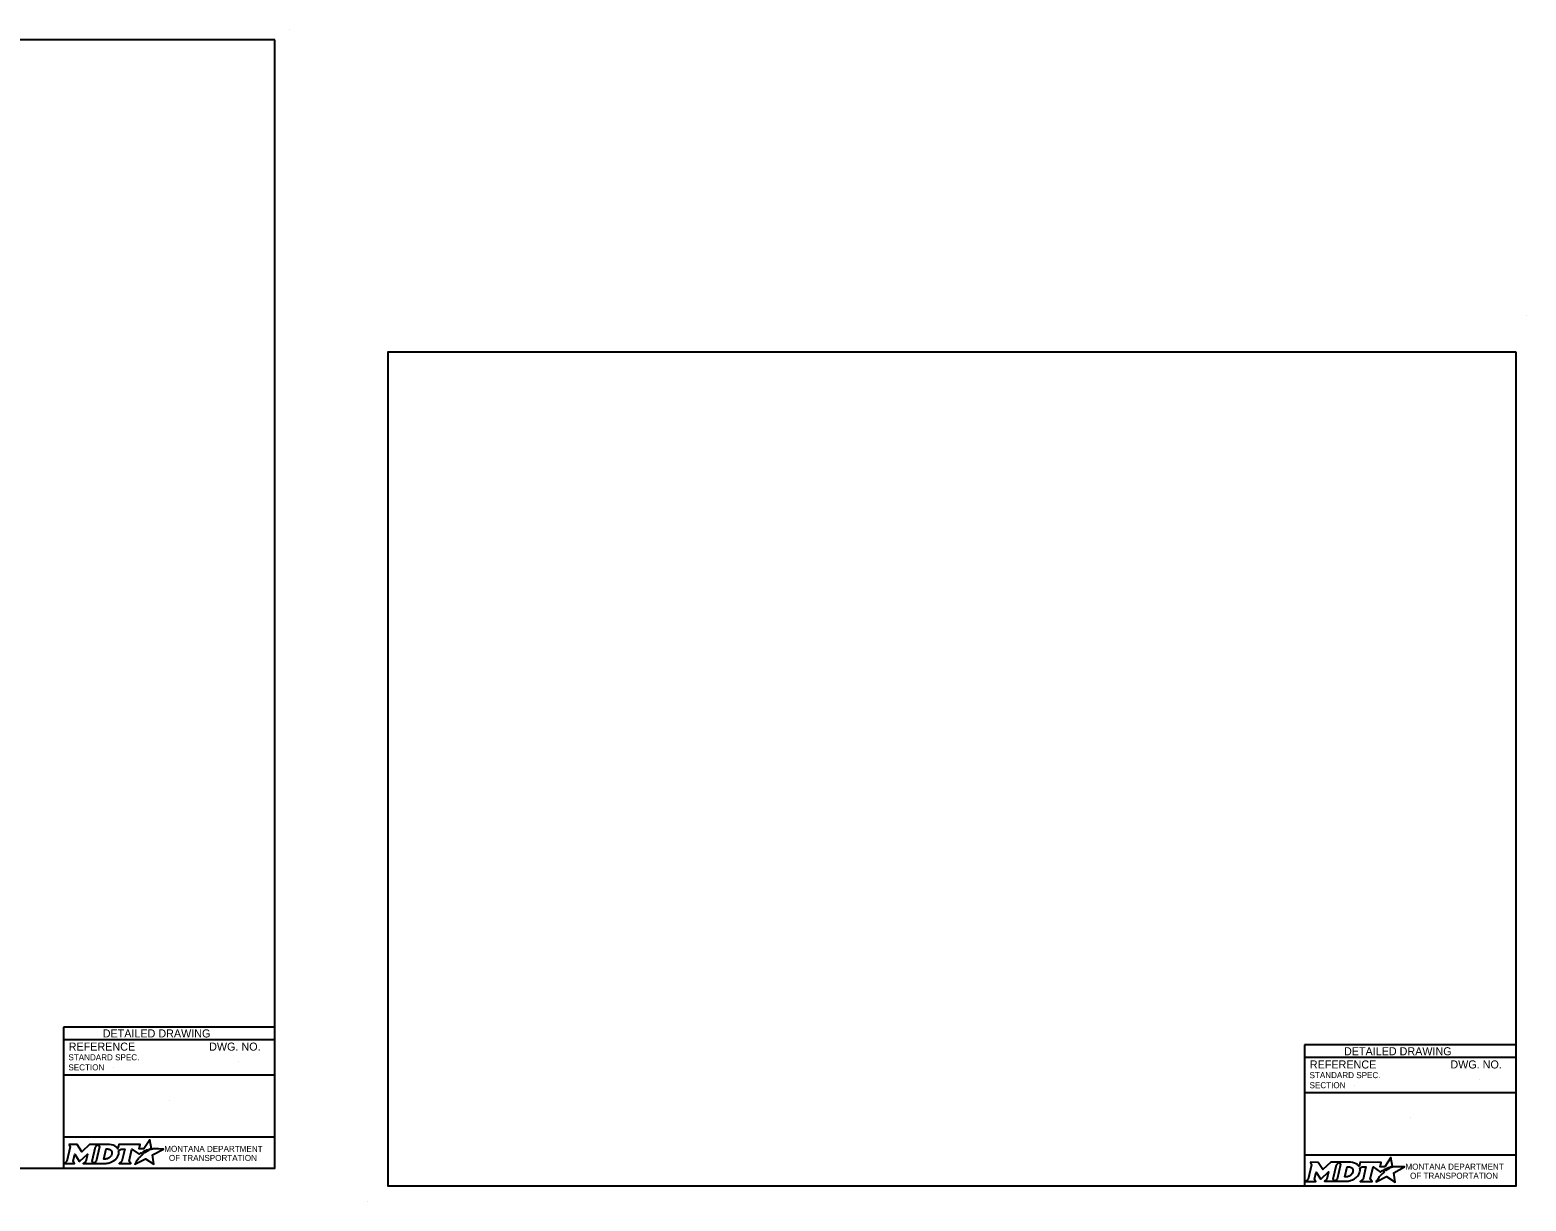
# Model space of a CAD drawing. Extents: x 49991.4 to 50021, y 49987.6 to 50011.4.
# Drawn here: x 50006.18 to 50021.04, y 49999.74 to 50011.36 of the extents above; entities that cross this region are included whole.
import ezdxf

# ---------------------------------------------------------------- set-up
doc = ezdxf.new("R2010")
doc.units = 0
for name, color, linetype in [('Default', 7, 'Continuous'), ('Level 1', 7, 'Continuous'), ('Level 2', 7, 'Continuous'), ('Level 4', 7, 'Continuous')]:
    doc.layers.add(name, color=color, linetype=linetype)

msp = doc.modelspace()

# ---------------------------------------------------------------- linework, layer by layer
at = {"layer": 'Default'}
for points in [[(50018.893, 50000.121), (50018.907, 50000.097), (50018.874, 49999.954), (50018.848, 49999.931), (50018.95, 49999.931), (50018.936, 49999.954), (50018.952, 50000.024), (50018.996, 49999.955), (50019.002, 49999.955), (50019.077, 50000.025), (50019.06, 49999.954), (50019.035, 49999.932), (50019.137, 49999.932), (50019.123, 49999.955), (50019.156, 50000.097)], [(50019.156, 50000.097), (50019.182, 50000.121), (50019.099, 50000.121), (50019.02, 50000.048), (50018.975, 50000.12), (50018.893, 50000.121)], [(50019.295, 50000.121), (50019.182, 50000.121), (50019.196, 50000.098), (50019.163, 49999.954), (50019.137, 49999.932), (50019.248, 49999.932)], [(50019.319, 50000.034), (50019.318, 50000.026), (50019.315, 50000.017), (50019.311, 50000.008), (50019.305, 50000.001), (50019.299, 49999.994), (50019.291, 49999.988), (50019.282, 49999.983), (50019.273, 49999.979), (50019.264, 49999.977), (50019.255, 49999.976), (50019.239, 49999.976), (50019.263, 50000.076), (50019.279, 50000.076), (50019.286, 50000.075), (50019.294, 50000.073), (50019.301, 50000.07), (50019.307, 50000.066), (50019.311, 50000.061), (50019.315, 50000.055), (50019.318, 50000.049), (50019.319, 50000.042), (50019.32, 50000.038), (50019.319, 50000.034)], [(50019.7, 50000.068), (50019.69, 50000.074), (50019.702, 50000.076), (50019.713, 50000.078), (50019.696, 50000.168), (50019.636, 50000.077), (50019.589, 50000.076), (50019.599, 50000.12), (50019.39, 50000.121), (50019.38, 50000.078), (50019.374, 50000.086)], [(50019.387, 50000.062), (50019.411, 50000.075), (50019.448, 50000.075), (50019.42, 49999.954), (50019.392, 49999.931), (50019.508, 49999.931), (50019.491, 49999.954), (50019.52, 50000.075), (50019.591, 50000.023), (50019.612, 50000.038), (50019.632, 50000.027)], [(50019.576, 49999.971), (50019.561, 49999.947), (50019.556, 49999.939), (50019.55, 49999.931), (50019.548, 49999.926), (50019.653, 49999.979), (50019.737, 49999.924), (50019.724, 50000.017), (50019.831, 50000.075), (50019.782, 50000.076), (50019.751, 50000.077), (50019.731, 50000.077), (50019.724, 50000.075), (50019.719, 50000.074), (50019.711, 50000.072), (50019.7, 50000.068)], [(50019.65, 50000.04), (50019.648, 50000.039), (50019.629, 50000.048), (50019.639, 50000.054), (50019.644, 50000.056), (50019.652, 50000.06), (50019.658, 50000.063), (50019.666, 50000.066), (50019.673, 50000.068), (50019.685, 50000.061), (50019.681, 50000.059), (50019.676, 50000.056), (50019.672, 50000.054), (50019.667, 50000.051), (50019.665, 50000.05), (50019.662, 50000.049), (50019.66, 50000.047), (50019.658, 50000.046), (50019.655, 50000.044), (50019.652, 50000.042), (50019.65, 50000.04)], [(50019.293, 49999.939), (50019.302, 49999.942), (50019.315, 49999.947), (50019.335, 49999.958)], [(50019.59, 49999.987), (50019.59, 49999.987)]]:
    msp.add_lwpolyline(points, dxfattribs=at)
for centre, radius, start, end in [((50019.319, 50000.042), 0.0709, 339.5329, 15.8582), ((50019.274, 50000.059), 0.118, 300.9103, 339.1383)]:
    msp.add_arc(centre, radius, start, end, dxfattribs=at)
for centre, major_axis, ratio, start_param, end_param in [((50019.293, 50000.073), (0.0834, -0.0037), 0.568097, 0.61298, 1.570796), ((50019.349, 50000.081), (0.0361, -0.0295), 0.469099, 1.225588, 1.570796), ((50019.248, 50000.08), (0, 0.148), 0.987302, 3.139398, 3.456847), ((50019.583, 49999.979), (-0.00694, -0.00806), 0.008222, 0, 3.137361), ((50019.6, 49999.997), (-0.0098, -0.0102), 0.016458, 3.141593, 6.279097), ((50019.621, 50000.017), (-0.0112, -0.0097), 0.021651, 3.157348, 6.283185)]:
    msp.add_ellipse(centre, major_axis=major_axis, ratio=ratio, start_param=start_param, end_param=end_param, dxfattribs=at)
at = {"layer": 'Level 1'}
for p, q in [((50008.765, 50011.363), (50008.765, 50011.363)), ((50021.038, 50008.524), (50021.038, 50008.524)), ((50009.537, 49999.736), (50009.537, 49999.736))]:
    msp.add_line(p, q, dxfattribs=at)
for points in [[(50008.615, 50011.263), (50000.336, 50011.263), (50000.336, 50000.062), (50008.615, 50000.062)], [(50020.938, 50008.165), (50009.737, 50008.165), (50009.737, 49999.886), (50020.938, 49999.886)]]:
    msp.add_lwpolyline(points, close=True, dxfattribs=at)
at = {"layer": 'Level 2'}
for p, q in [((50008.615, 50001.462), (50006.515, 50001.462)), ((50006.515, 50001.462), (50006.515, 50000.062)), ((50008.615, 50001.337), (50006.515, 50001.337)), ((50008.251, 50001.122), (50008.251, 50001.122)), ((50008.615, 50000.987), (50006.515, 50000.987)), ((50007.009, 50001.063), (50007.009, 50001.063)), ((50007.565, 50000.738), (50007.565, 50000.738)), ((50008.615, 50000.369), (50006.515, 50000.369))]:
    msp.add_line(p, q, dxfattribs=at)
for points in [[(50006.57, 50000.297), (50006.584, 50000.274), (50006.551, 50000.131), (50006.525, 50000.108), (50006.627, 50000.108), (50006.613, 50000.131), (50006.629, 50000.201), (50006.673, 50000.132), (50006.678, 50000.132), (50006.753, 50000.202), (50006.737, 50000.13), (50006.712, 50000.108), (50006.814, 50000.108), (50006.8, 50000.132), (50006.833, 50000.274)], [(50006.833, 50000.274), (50006.859, 50000.297), (50006.776, 50000.297), (50006.697, 50000.224), (50006.652, 50000.297), (50006.57, 50000.297)], [(50006.972, 50000.297), (50006.859, 50000.297), (50006.873, 50000.275), (50006.839, 50000.131), (50006.814, 50000.108), (50006.925, 50000.108)], [(50006.996, 50000.211), (50006.995, 50000.203), (50006.992, 50000.193), (50006.988, 50000.185), (50006.982, 50000.178), (50006.976, 50000.171), (50006.968, 50000.164), (50006.959, 50000.16), (50006.95, 50000.156), (50006.941, 50000.154), (50006.932, 50000.153), (50006.916, 50000.153), (50006.94, 50000.253), (50006.956, 50000.253), (50006.963, 50000.252), (50006.971, 50000.25), (50006.977, 50000.247), (50006.983, 50000.243), (50006.988, 50000.238), (50006.992, 50000.232), (50006.995, 50000.226), (50006.996, 50000.218), (50006.996, 50000.215), (50006.996, 50000.211)], [(50007.377, 50000.245), (50007.367, 50000.25), (50007.378, 50000.253), (50007.39, 50000.255), (50007.373, 50000.345), (50007.313, 50000.254), (50007.266, 50000.253), (50007.276, 50000.297), (50007.067, 50000.297), (50007.057, 50000.255), (50007.051, 50000.263)], [(50007.064, 50000.238), (50007.088, 50000.251), (50007.125, 50000.251), (50007.097, 50000.131), (50007.069, 50000.108), (50007.185, 50000.108), (50007.168, 50000.131), (50007.196, 50000.251), (50007.268, 50000.2), (50007.289, 50000.215), (50007.309, 50000.204)], [(50007.253, 50000.148), (50007.237, 50000.124), (50007.233, 50000.116), (50007.227, 50000.107), (50007.225, 50000.103), (50007.33, 50000.156), (50007.414, 50000.101), (50007.401, 50000.194), (50007.508, 50000.252), (50007.458, 50000.253), (50007.428, 50000.253), (50007.407, 50000.254), (50007.401, 50000.252), (50007.396, 50000.251), (50007.387, 50000.249), (50007.377, 50000.245)], [(50007.327, 50000.217), (50007.324, 50000.215), (50007.306, 50000.225), (50007.316, 50000.231), (50007.32, 50000.233), (50007.329, 50000.237), (50007.335, 50000.239), (50007.343, 50000.243), (50007.35, 50000.245), (50007.362, 50000.238), (50007.358, 50000.236), (50007.353, 50000.233), (50007.349, 50000.231), (50007.344, 50000.228), (50007.342, 50000.227), (50007.339, 50000.225), (50007.337, 50000.224), (50007.334, 50000.222), (50007.332, 50000.221), (50007.329, 50000.219), (50007.327, 50000.217)], [(50006.97, 50000.116), (50006.979, 50000.118), (50006.992, 50000.124), (50007.012, 50000.135)], [(50007.267, 50000.164), (50007.267, 50000.164)]]:
    msp.add_lwpolyline(points, dxfattribs=at)
for centre, radius, start, end in [((50006.995, 50000.219), 0.0709, 339.5329, 15.8582), ((50006.951, 50000.236), 0.118, 300.9103, 339.1383)]:
    msp.add_arc(centre, radius, start, end, dxfattribs=at)
for centre, major_axis, ratio, start_param, end_param in [((50006.97, 50000.25), (0.0834, -0.0037), 0.568097, 0.61298, 1.570796), ((50007.026, 50000.257), (0.0361, -0.0295), 0.469099, 1.225588, 1.570796), ((50007.297, 50000.194), (-0.0112, -0.0097), 0.021651, 3.157348, 6.283185), ((50006.925, 50000.257), (0, 0.148), 0.987302, 3.139398, 3.456847), ((50007.26, 50000.156), (-0.00694, -0.00806), 0.008222, 0, 3.137361), ((50007.276, 50000.174), (-0.0098, -0.0102), 0.016458, 3.141593, 6.279097)]:
    msp.add_ellipse(centre, major_axis=major_axis, ratio=ratio, start_param=start_param, end_param=end_param, dxfattribs=at)
at = {"layer": 'Level 4'}
for p, q in [((50020.938, 50001.286), (50018.838, 50001.286)), ((50018.838, 50001.286), (50018.838, 49999.886)), ((50020.938, 50001.161), (50018.838, 50001.161)), ((50020.574, 50000.946), (50020.574, 50000.946)), ((50020.938, 50000.811), (50018.838, 50000.811)), ((50019.332, 50000.886), (50019.332, 50000.886)), ((50019.888, 50000.562), (50019.888, 50000.562)), ((50020.938, 50000.193), (50018.838, 50000.193))]:
    msp.add_line(p, q, dxfattribs=at)

# ---------------------------------------------------------------- texts
at = {"layer": 'Default'}
for s, p in [('MONTANA DEPARTMENT', (50019.84, 50000.047)), ('OF TRANSPORTATION', (50019.886, 49999.957))]:
    msp.add_text(s, height=0.06, rotation=360, dxfattribs=at).set_placement(p)
at = {"layer": 'Level 2'}
for s, height, p in [('DETAILED DRAWING', 0.0799, (50006.906, 50001.36)), ('REFERENCE', 0.08, (50006.568, 50001.229)), ('DWG. NO.', 0.08, (50007.962, 50001.229)), ('STANDARD SPEC.', 0.06, (50006.565, 50001.133)), ('SECTION', 0.06, (50006.565, 50001.033))]:
    msp.add_text(s, height=height, dxfattribs=at).set_placement(p)
for s, p in [('MONTANA DEPARTMENT', (50007.517, 50000.224)), ('OF TRANSPORTATION', (50007.563, 50000.134))]:
    msp.add_text(s, height=0.06, rotation=360, dxfattribs=at).set_placement(p)
at = {"layer": 'Level 4'}
for s, height, p in [('DETAILED DRAWING', 0.0799, (50019.23, 50001.183)), ('REFERENCE', 0.08, (50018.891, 50001.052)), ('DWG. NO.', 0.08, (50020.286, 50001.052)), ('STANDARD SPEC.', 0.06, (50018.888, 50000.956)), ('SECTION', 0.06, (50018.888, 50000.856))]:
    msp.add_text(s, height=height, dxfattribs=at).set_placement(p)

doc.saveas('drawing.dxf')
